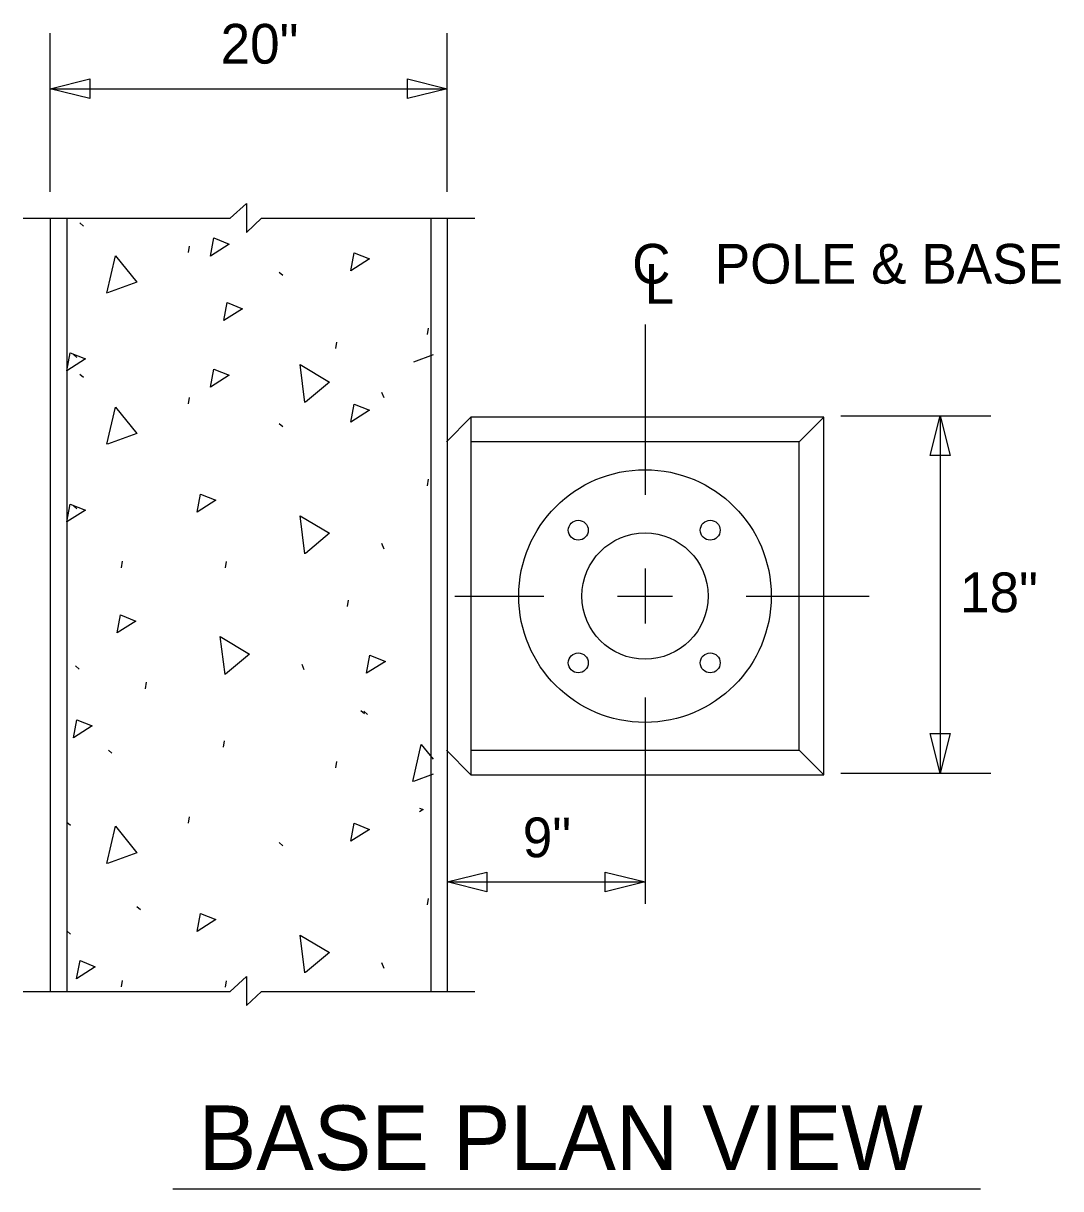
# Model space of a CAD drawing. Extents: x 10109.1 to 10158.1, y 10066 to 10132.7.
# Drawn here: x 10122.59 to 10140.01, y 10113.16 to 10132.71 of the extents above; entities that cross this region are included whole.
import ezdxf

# ---------------------------------------------------------------- set-up
doc = ezdxf.new("R2010")
doc.units = 0
for name, color, linetype in [('G-ANNO-TEXT', 7, 'Continuous'), ('G-DETL-LINE', 7, 'Continuous'), ('G-DETL-OTLN', 7, 'Continuous'), ('G-DETL-PATT', 7, 'Continuous'), ('Level 49', 7, 'Continuous')]:
    doc.layers.add(name, color=color, linetype=linetype)

msp = doc.modelspace()

# ---------------------------------------------------------------- linework, layer by layer
at = {"layer": 'G-ANNO-TEXT'}
for p, q in [((10123.04, 10129.887), (10123.04, 10132.549)), ((10129.706, 10129.887), (10129.706, 10132.549)), ((10123.04, 10131.615), (10129.706, 10131.615)), ((10126.064, 10129.44), (10126.337, 10129.691)), ((10126.337, 10129.691), (10126.337, 10129.203)), ((10122.588, 10129.44), (10126.064, 10129.44)), ((10126.337, 10129.203), (10126.589, 10129.44)), ((10126.589, 10129.44), (10130.171, 10129.44)), ((10133.027, 10127.658), (10133.027, 10124.801)), ((10136.317, 10126.127), (10138.832, 10126.127)), ((10137.982, 10126.127), (10137.982, 10120.127)), ((10133.027, 10123.561), (10133.027, 10122.642)), ((10129.835, 10123.101), (10131.327, 10123.101)), ((10132.567, 10123.101), (10133.486, 10123.101)), ((10134.727, 10123.101), (10136.793, 10123.101)), ((10133.027, 10121.401), (10133.027, 10117.937)), ((10136.317, 10120.127), (10138.832, 10120.127)), ((10129.706, 10118.303), (10133.027, 10118.303)), ((10126.064, 10116.466), (10126.337, 10116.717)), ((10126.337, 10116.717), (10126.337, 10116.229)), ((10122.588, 10116.466), (10126.064, 10116.466)), ((10126.337, 10116.229), (10126.589, 10116.466)), ((10126.589, 10116.466), (10130.171, 10116.466)), ((10125.099, 10113.156), (10138.662, 10113.156))]:
    msp.add_line(p, q, dxfattribs=at)
for points in [[(10123.706, 10131.448), (10123.04, 10131.615), (10123.706, 10131.781)], [(10129.04, 10131.781), (10129.706, 10131.615), (10129.04, 10131.448)], [(10137.816, 10125.46), (10137.982, 10126.127), (10138.149, 10125.46)], [(10138.149, 10120.793), (10137.982, 10120.127), (10137.816, 10120.793)], [(10130.373, 10118.136), (10129.706, 10118.303), (10130.373, 10118.469)], [(10132.36, 10118.469), (10133.027, 10118.303), (10132.36, 10118.136)]]:
    msp.add_lwpolyline(points, close=True, dxfattribs=at)
at = {"layer": 'G-DETL-LINE'}
for p, q in [((10123.04, 10129.44), (10123.04, 10116.466)), ((10123.318, 10129.44), (10123.318, 10116.466)), ((10129.429, 10129.44), (10129.429, 10116.466)), ((10129.706, 10129.44), (10129.706, 10116.466)), ((10129.693, 10125.69), (10130.105, 10126.101)), ((10130.105, 10126.101), (10130.105, 10120.101)), ((10136.027, 10126.101), (10130.105, 10126.101)), ((10135.614, 10125.69), (10136.027, 10126.101)), ((10136.027, 10120.101), (10136.027, 10126.101)), ((10135.614, 10125.69), (10130.105, 10125.69)), ((10135.614, 10120.514), (10135.614, 10125.69)), ((10129.693, 10120.514), (10130.105, 10120.101)), ((10130.105, 10120.514), (10135.614, 10120.514)), ((10135.614, 10120.514), (10136.027, 10120.101)), ((10130.105, 10120.101), (10136.027, 10120.101))]:
    msp.add_line(p, q, dxfattribs=at)
at = {"layer": 'G-DETL-OTLN'}
for centre, radius in [((10133.027, 10123.101), 2.12), ((10131.906, 10124.206), 0.167), ((10134.122, 10124.206), 0.167), ((10131.906, 10121.98), 0.167), ((10134.122, 10121.98), 0.167)]:
    msp.add_circle(centre, radius, dxfattribs=at)
at = {"layer": 'G-DETL-PATT'}
for p, q in [((10123.539, 10129.363), (10123.6, 10129.31)), ((10125.361, 10128.864), (10125.378, 10128.972)), ((10126.885, 10128.537), (10126.945, 10128.484)), ((10129.372, 10127.491), (10129.389, 10127.599)), ((10127.836, 10127.253), (10127.853, 10127.361)), ((10123.429, 10127.156), (10123.489, 10127.103)), ((10123.539, 10126.825), (10123.6, 10126.772)), ((10125.361, 10126.326), (10125.378, 10126.434)), ((10128.604, 10126.525), (10128.641, 10126.432)), ((10126.885, 10125.999), (10126.945, 10125.946)), ((10129.372, 10124.953), (10129.389, 10125.061)), ((10123.429, 10124.618), (10123.489, 10124.565)), ((10128.604, 10123.987), (10128.641, 10123.894)), ((10124.236, 10123.576), (10124.253, 10123.684)), ((10125.983, 10123.573), (10126, 10123.681)), ((10128.03, 10122.926), (10128.047, 10123.034)), ((10123.466, 10121.928), (10123.526, 10121.876)), ((10127.262, 10121.96), (10127.299, 10121.867)), ((10124.641, 10121.547), (10124.658, 10121.655)), ((10128.255, 10121.182), (10128.315, 10121.129)), ((10128.305, 10121.169), (10128.365, 10121.116)), ((10124.017, 10120.515), (10124.077, 10120.462)), ((10125.95, 10120.564), (10125.967, 10120.672)), ((10127.836, 10120.218), (10127.853, 10120.326)), ((10125.361, 10119.29), (10125.378, 10119.398)), ((10123.319, 10119.308), (10123.379, 10119.255)), ((10126.885, 10118.963), (10126.945, 10118.91)), ((10129.372, 10117.917), (10129.389, 10118.025)), ((10124.495, 10117.894), (10124.555, 10117.841)), ((10123.319, 10117.481), (10123.379, 10117.428)), ((10128.604, 10116.952), (10128.641, 10116.858)), ((10124.236, 10116.541), (10124.253, 10116.649)), ((10125.983, 10116.538), (10126, 10116.646))]:
    msp.add_line(p, q, dxfattribs=at)
for points in [[(10125.732, 10128.807), (10125.789, 10129.11), (10126.047, 10129.006), (10125.732, 10128.807)], [(10123.991, 10128.186), (10124.134, 10128.811), (10124.494, 10128.367), (10124.001, 10128.189)], [(10128.085, 10128.559), (10128.142, 10128.862), (10128.4, 10128.759), (10128.085, 10128.559)], [(10125.956, 10127.723), (10126.013, 10128.026), (10126.27, 10127.923), (10125.956, 10127.723)], [(10123.317, 10126.882), (10123.374, 10127.184), (10123.632, 10127.081), (10123.317, 10126.882)], [(10127.317, 10126.35), (10127.238, 10126.986), (10127.728, 10126.692), (10127.326, 10126.356)], [(10129.471, 10127.148), (10129.137, 10127.027)], [(10125.732, 10126.608), (10125.789, 10126.91), (10126.047, 10126.807), (10125.732, 10126.608)], [(10123.991, 10125.648), (10124.134, 10126.273), (10124.494, 10125.829), (10124.001, 10125.651)], [(10128.085, 10126.021), (10128.142, 10126.324), (10128.4, 10126.221), (10128.085, 10126.021)], [(10123.317, 10124.344), (10123.374, 10124.646), (10123.632, 10124.543), (10123.317, 10124.344)], [(10125.505, 10124.509), (10125.562, 10124.811), (10125.819, 10124.708), (10125.505, 10124.509)], [(10127.317, 10123.812), (10127.238, 10124.448), (10127.728, 10124.154), (10127.326, 10123.818)], [(10124.163, 10122.482), (10124.22, 10122.784), (10124.477, 10122.681), (10124.163, 10122.482)], [(10125.975, 10121.785), (10125.896, 10122.421), (10126.386, 10122.127), (10125.984, 10121.792)], [(10128.353, 10121.806), (10128.409, 10122.108), (10128.667, 10122.005), (10128.353, 10121.806)], [(10123.428, 10120.723), (10123.485, 10121.026), (10123.742, 10120.922), (10123.428, 10120.723)], [(10129.127, 10119.989), (10129.27, 10120.613), (10129.471, 10120.365)], [(10129.471, 10120.113), (10129.137, 10119.992)], [(10129.242, 10119.543), (10129.302, 10119.519), (10129.242, 10119.481)], [(10123.991, 10118.613), (10124.134, 10119.237), (10124.494, 10118.794), (10124.001, 10118.616)], [(10128.085, 10118.986), (10128.142, 10119.289), (10128.4, 10119.185), (10128.085, 10118.986)], [(10125.505, 10117.473), (10125.562, 10117.776), (10125.819, 10117.672), (10125.505, 10117.473)], [(10127.317, 10116.777), (10127.238, 10117.412), (10127.728, 10117.119), (10127.326, 10116.783)], [(10123.483, 10116.68), (10123.54, 10116.983), (10123.797, 10116.879), (10123.483, 10116.68)]]:
    msp.add_lwpolyline(points, dxfattribs=at)
at = {"layer": 'Level 49'}
msp.add_circle((10133.027, 10123.101), 1.06, dxfattribs=at)

# ---------------------------------------------------------------- texts
at = {"layer": 'G-ANNO-TEXT'}
for s, height, p in [('20"', 0.6667, (10125.9, 10132.036)), ('C   POLE & BASE', 0.66667, (10132.811, 10128.344)), ('L', 0.667, (10133.02, 10128.006)), ('18"', 0.6667, (10138.316, 10122.83)), ('9"', 0.6667, (10130.974, 10118.718)), ('BASE PLAN VIEW', 1.08333, (10125.533, 10113.47))]:
    msp.add_text(s, height=height, dxfattribs=at).set_placement(p)

doc.saveas('drawing.dxf')
